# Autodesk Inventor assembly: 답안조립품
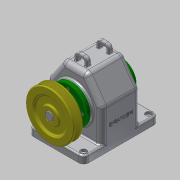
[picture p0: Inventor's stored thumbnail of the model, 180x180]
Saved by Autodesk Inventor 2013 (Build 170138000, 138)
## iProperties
Created: 2016-12
Part Number: 답안조립품
Document SubType Name: Assembly
Designer: Administrator
Author: Administrator
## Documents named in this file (15)
- C:\Users\Administrator\Desktop\461207V1005\답안조립품.iam
- C:\Users\Administrator\Desktop\461207V1005\본체.ipt
- C:\Users\Administrator\Desktop\461207V1005\공용부품\V-벨트풀리.ipt
- C:\Users\Administrator\Desktop\461207V1005\공용부품\뒤커버.ipt
- C:\Users\Administrator\Desktop\461207V1005\공용부품\멈춤나사 - M4x10.ipt
- C:\Users\Administrator\Desktop\461207V1005\공용부품\베어링 6203.ipt
- C:\Users\Administrator\Desktop\461207V1005\공용부품\볼트 M3 x 8.ipt
- C:\Users\Administrator\Desktop\461207V1005\공용부품\볼트 M3 x 10.ipt
- C:\Users\Administrator\Desktop\461207V1005\공용부품\부시.ipt
- C:\Users\Administrator\Desktop\461207V1005\공용부품\스퍼기어.ipt
- C:\Users\Administrator\Desktop\461207V1005\공용부품\앞커버.ipt
- C:\Users\Administrator\Desktop\461207V1005\공용부품\오일씰 28 40 8.ipt
- C:\Users\Administrator\Desktop\461207V1005\공용부품\축.ipt
- C:\Users\Administrator\Desktop\461207V1005\공용부품\키 - 5 x 5 x 18.ipt
- C:\Users\Administrator\Desktop\461207V1005\공용부품\키 - 6 x 6 x 22.ipt
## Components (9 placed, 3 different names)
1. V-벨트풀리:1
2. ISO 4762 M3 x 8:1
3. ISO 4762 M3 x 8:2
4. ISO 4762 M3 x 8:3
5. ISO 4762 M3 x 8:4
6. ISO 4762 M3 x 10:1
7. ISO 4762 M3 x 10:2
8. ISO 4762 M3 x 10:3
9. ISO 4762 M3 x 10:4
